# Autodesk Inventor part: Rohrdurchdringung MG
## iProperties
Category: 200 Bauteil
Created: 2009-05
Part Number: Rohrdurchdringung MG
Material: 1.0037 St 37-2
Document SubType Name: Blech
Designer: M. Fiedler
Density: 7.85 g/cm^3
Mass: 1472.89 g
Surface Area: 799.611 cm^2
Volume: 187.629 cm^3
Author: M. Fiedler
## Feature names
1. Trennen2
2. Grobblech1
3. Ausklinkung3
